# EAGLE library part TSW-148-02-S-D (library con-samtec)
THROUGH-HOLE .025" SQ POST HEADER Source: Samtec TSW.pdf
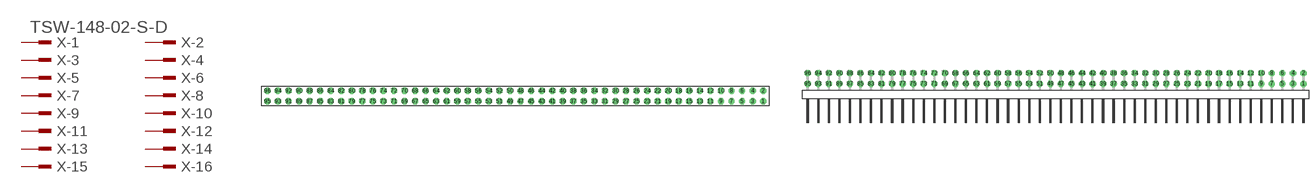
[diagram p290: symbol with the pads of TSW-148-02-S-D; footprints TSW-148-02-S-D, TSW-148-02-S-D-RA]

Designator prefix X; gates -1=MPINV -2=MPIN -3=MPIN -4=MPIN -5=MPIN -6=MPIN -7=MPIN -8=MPIN -9=MPIN -10=MPIN -11=MPIN -12=MPIN -13=MPIN -14=MPIN -15=MPIN -16=MPIN -17=MPIN -18=MPIN -19=MPIN -20=MPIN -21=MPIN -22=MPIN -23=MPIN -24=MPIN -25=MPIN -26=MPIN -27=MPIN -28=MPIN -29=MPIN -30=MPIN -31=MPIN -32=MPIN -33=MPIN -34=MPIN -35=MPIN -36=MPIN -37=MPIN -38=MPIN -39=MPIN -40=MPIN -41=MPIN -42=MPIN -43=MPIN -44=MPIN -45=MPIN -46=MPIN -47=MPIN -48=MPIN -49=MPIN -50=MPIN -51=MPIN -52=MPIN -53=MPIN -54=MPIN -55=MPIN -56=MPIN -57=MPIN -58=MPIN -59=MPIN -60=MPIN -61=MPIN -62=MPIN -63=MPIN -64=MPIN -65=MPIN -66=MPIN -67=MPIN -68=MPIN -69=MPIN -70=MPIN -71=MPIN -72=MPIN -73=MPIN -74=MPIN -75=MPIN -76=MPIN -77=MPIN -78=MPIN -79=MPIN -80=MPIN -81=MPIN -82=MPIN -83=MPIN -84=MPIN -85=MPIN -86=MPIN -87=MPIN -88=MPIN -89=MPIN -90=MPIN -91=MPIN -92=MPIN -93=MPIN -94=MPIN -95=MPIN -96=MPIN

## TSW-148-02-S-D (OC_FARNELL: unknown; OC_NEWARK: unknown)  [TSW-148-02-S-D]
1  -1:1  pas
2  -2:1  pas
3  -3:1  pas
4  -4:1  pas
5  -5:1  pas
6  -6:1  pas
7  -7:1  pas
8  -8:1  pas
9  -9:1  pas
10  -10:1  pas
11  -11:1  pas
12  -12:1  pas
13  -13:1  pas
14  -14:1  pas
15  -15:1  pas
16  -16:1  pas
17  -17:1  pas
18  -18:1  pas
19  -19:1  pas
20  -20:1  pas
21  -21:1  pas
22  -22:1  pas
23  -23:1  pas
24  -24:1  pas
25  -25:1  pas
26  -26:1  pas
27  -27:1  pas
28  -28:1  pas
29  -29:1  pas
30  -30:1  pas
31  -31:1  pas
32  -32:1  pas
33  -33:1  pas
34  -34:1  pas
35  -35:1  pas
36  -36:1  pas
37  -37:1  pas
38  -38:1  pas
39  -39:1  pas
40  -40:1  pas
41  -41:1  pas
42  -42:1  pas
43  -43:1  pas
44  -44:1  pas
45  -45:1  pas
46  -46:1  pas
47  -47:1  pas
48  -48:1  pas
49  -49:1  pas
50  -50:1  pas
51  -51:1  pas
52  -52:1  pas
53  -53:1  pas
54  -54:1  pas
55  -55:1  pas
56  -56:1  pas
57  -57:1  pas
58  -58:1  pas
59  -59:1  pas
60  -60:1  pas
61  -61:1  pas
62  -62:1  pas
63  -63:1  pas
64  -64:1  pas
65  -65:1  pas
66  -66:1  pas
67  -67:1  pas
68  -68:1  pas
69  -69:1  pas
70  -70:1  pas
71  -71:1  pas
72  -72:1  pas
73  -73:1  pas
74  -74:1  pas
75  -75:1  pas
76  -76:1  pas
77  -77:1  pas
78  -78:1  pas
79  -79:1  pas
80  -80:1  pas
81  -81:1  pas
82  -82:1  pas
83  -83:1  pas
84  -84:1  pas
85  -85:1  pas
86  -86:1  pas
87  -87:1  pas
88  -88:1  pas
89  -89:1  pas
90  -90:1  pas
91  -91:1  pas
92  -92:1  pas
93  -93:1  pas
94  -94:1  pas
95  -95:1  pas
96  -96:1  pas

## TSW-148-02-S-D-RA (OC_FARNELL: unknown; OC_NEWARK: unknown)  [TSW-148-02-S-D-RA]
Pads as for TSW-148-02-S-D

## Footprint TSW-148-02-S-D (pad centres in mm)
THROUGH-HOLE .025" SQ POST HEADER Source: Samtec TSW.pdf
drill 1 pad 1.5 octagon: 1 59.69,-1.27; 2 59.69,1.27; 3 57.15,-1.27; 4 57.15,1.27; 5 54.61,-1.27; 6 54.61,1.27; 7 52.07,-1.27; 8 52.07,1.27; 9 49.53,-1.27; 10 49.53,1.27; 11 46.99,-1.27; 12 46.99,1.27; 13 44.45,-1.27; 14 44.45,1.27; 15 41.91,-1.27; 16 41.91,1.27; 17 39.37,-1.27; 18 39.37,1.27; 19 36.83,-1.27; 20 36.83,1.27; 21 34.29,-1.27; 22 34.29,1.27; 23 31.75,-1.27; 24 31.75,1.27; 25 29.21,-1.27; 26 29.21,1.27; 27 26.67,-1.27; 28 26.67,1.27; 29 24.13,-1.27; 30 24.13,1.27; 31 21.59,-1.27; 32 21.59,1.27; 33 19.05,-1.27; 34 19.05,1.27; 35 16.51,-1.27; 36 16.51,1.27; 37 13.97,-1.27; 38 13.97,1.27; 39 11.43,-1.27; 40 11.43,1.27; 41 8.89,-1.27; 42 8.89,1.27; 43 6.35,-1.27; 44 6.35,1.27; 45 3.81,-1.27; 46 3.81,1.27; 47 1.27,-1.27; 48 1.27,1.27; 49 -1.27,-1.27; 50 -1.27,1.27; 51 -3.81,-1.27; 52 -3.81,1.27; 53 -6.35,-1.27; 54 -6.35,1.27; 55 -8.89,-1.27; 56 -8.89,1.27; 57 -11.43,-1.27; 58 -11.43,1.27; 59 -13.97,-1.27; 60 -13.97,1.27; 61 -16.51,-1.27; 62 -16.51,1.27; 63 -19.05,-1.27; 64 -19.05,1.27; 65 -21.59,-1.27; 66 -21.59,1.27; 67 -24.13,-1.27; 68 -24.13,1.27; 69 -26.67,-1.27; 70 -26.67,1.27; 71 -29.21,-1.27; 72 -29.21,1.27; 73 -31.75,-1.27; 74 -31.75,1.27; 75 -34.29,-1.27; 76 -34.29,1.27; 77 -36.83,-1.27; 78 -36.83,1.27; 79 -39.37,-1.27; 80 -39.37,1.27; 81 -41.91,-1.27; 82 -41.91,1.27; 83 -44.45,-1.27; 84 -44.45,1.27; 85 -46.99,-1.27; 86 -46.99,1.27; 87 -49.53,-1.27; 88 -49.53,1.27; 89 -52.07,-1.27; 90 -52.07,1.27; 91 -54.61,-1.27; 92 -54.61,1.27; 93 -57.15,-1.27; 94 -57.15,1.27; 95 -59.69,-1.27; 96 -59.69,1.27

## Footprint TSW-148-02-S-D-RA (pad centres in mm)
THROUGH-HOLE .025" SQ POST HEADER Source: Samtec TSW.pdf
drill 1 pad 1.5 octagon: 1 59.69,1.524; 2 59.69,4.064; 3 57.15,1.524; 4 57.15,4.064; 5 54.61,1.524; 6 54.61,4.064; 7 52.07,1.524; 8 52.07,4.064; 9 49.53,1.524; 10 49.53,4.064; 11 46.99,1.524; 12 46.99,4.064; 13 44.45,1.524; 14 44.45,4.064; 15 41.91,1.524; 16 41.91,4.064; 17 39.37,1.524; 18 39.37,4.064; 19 36.83,1.524; 20 36.83,4.064; 21 34.29,1.524; 22 34.29,4.064; 23 31.75,1.524; 24 31.75,4.064; 25 29.21,1.524; 26 29.21,4.064; 27 26.67,1.524; 28 26.67,4.064; 29 24.13,1.524; 30 24.13,4.064; 31 21.59,1.524; 32 21.59,4.064; 33 19.05,1.524; 34 19.05,4.064; 35 16.51,1.524; 36 16.51,4.064; 37 13.97,1.524; 38 13.97,4.064; 39 11.43,1.524; 40 11.43,4.064; 41 8.89,1.524; 42 8.89,4.064; 43 6.35,1.524; 44 6.35,4.064; 45 3.81,1.524; 46 3.81,4.064; 47 1.27,1.524; 48 1.27,4.064; 49 -1.27,1.524; 50 -1.27,4.064; 51 -3.81,1.524; 52 -3.81,4.064; 53 -6.35,1.524; 54 -6.35,4.064; 55 -8.89,1.524; 56 -8.89,4.064; 57 -11.43,1.524; 58 -11.43,4.064; 59 -13.97,1.524; 60 -13.97,4.064; 61 -16.51,1.524; 62 -16.51,4.064; 63 -19.05,1.524; 64 -19.05,4.064; 65 -21.59,1.524; 66 -21.59,4.064; 67 -24.13,1.524; 68 -24.13,4.064; 69 -26.67,1.524; 70 -26.67,4.064; 71 -29.21,1.524; 72 -29.21,4.064; 73 -31.75,1.524; 74 -31.75,4.064; 75 -34.29,1.524; 76 -34.29,4.064; 77 -36.83,1.524; 78 -36.83,4.064; 79 -39.37,1.524; 80 -39.37,4.064; 81 -41.91,1.524; 82 -41.91,4.064; 83 -44.45,1.524; 84 -44.45,4.064; 85 -46.99,1.524; 86 -46.99,4.064; 87 -49.53,1.524; 88 -49.53,4.064; 89 -52.07,1.524; 90 -52.07,4.064; 91 -54.61,1.524; 92 -54.61,4.064; 93 -57.15,1.524; 94 -57.15,4.064; 95 -59.69,1.524; 96 -59.69,4.064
